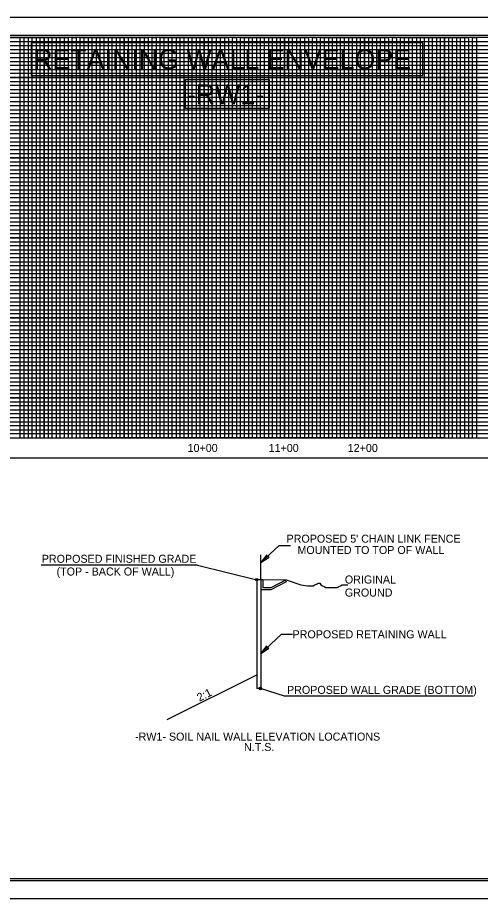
# Model space of a CAD drawing. Extents: x 505237 to 506921, y 424821 to 425921.
# Drawn here: x 505821 to 506398, y 424821 to 425921 of the extents above; entities that cross this region are included whole.
import ezdxf

# ---------------------------------------------------------------- set-up
doc = ezdxf.new("R2010")
doc.units = 0
for name, color, linetype in [('Exist Vertical Profile Ground Line', 7, 'Continuous'), ('Exist Vertical Profile Vertical Axis Label', 7, 'Continuous'), ('Matchline', 7, 'Continuous'), ('Prop Horizontal Alignment Station Label', 7, 'Continuous'), ('Prop North Arrow NAD83 for Plan Sheets CELL', 7, 'Continuous'), ('Prop Vertical Profile Grade', 7, 'Continuous'), ('Scratch_Level_6', 7, 'Continuous'), ('Sheet Clip Boundary CELL', 7, 'Continuous'), ('Sheet Cutting Line CELL', 7, 'Continuous'), ('Sheet DOT Grid CELL', 7, 'Continuous'), ('Sheet Layout Plan Border', 7, 'Continuous'), ('Sheet Plot Border Inside CELL', 7, 'Continuous'), ('Sheet Plot Border Outside CELL', 7, 'Continuous'), ('Sheet Profile Grid Major CELL', 7, 'Continuous'), ('Sheet Sticker Incomplete CELL', 7, 'Continuous'), ('Typical Text Label CELL', 7, 'Continuous')]:
    doc.layers.add(name, color=color, linetype=linetype)

msp = doc.modelspace()

# ---------------------------------------------------------------- linework, layer by layer
at = {"layer": 'Exist Vertical Profile Ground Line'}
for q in [(506123.7, 425218.6), (506174.4, 425212.2)]:
    msp.add_line((506157.2, 425217.9), q, dxfattribs=at)
msp.add_lwpolyline([(506174.4, 425212.2), (506182.6, 425211.1), (506184.7, 425211.1), (506187.8, 425211.1), (506189.8, 425211.1), (506191.9, 425212.2), (506193.9, 425213.2), (506196, 425214.2), (506198.1, 425214.2), (506199.1, 425212.2), (506201.2, 425211.1), (506203.2, 425210.1), (506205.3, 425209.1), (506207.3, 425209.1), (506209.4, 425209.1), (506211.4, 425209.1), (506213.5, 425209.1), (506215.6, 425209.1), (506217.6, 425209.1), (506219.7, 425209.1), (506221.7, 425210.1), (506223.8, 425211.1), (506225.9, 425212.2), (506228.9, 425212.2), (506231, 425212.2), (506233.1, 425212.2)], dxfattribs=at)
at = {"layer": 'Matchline'}
msp.add_line((505403.7, 425870.7), (506703.7, 425870.7), dxfattribs=at)
for points in [[(505778.7, 425395.7), (505828.7, 425395.7), (505828.7, 425895.7), (505878.7, 425895.7), (505878.7, 425395.7), (505928.7, 425395.7), (505928.7, 425895.7), (505978.7, 425895.7), (505978.7, 425395.7), (506028.7, 425395.7), (506028.7, 425395.7), (506028.7, 425895.7), (506078.7, 425895.7), (506078.7, 425395.7), (506128.7, 425395.7), (506128.7, 425895.7), (506178.7, 425895.7), (506178.7, 425395.7), (506228.7, 425395.7), (506228.7, 425895.7), (506278.7, 425895.7), (506278.7, 425395.7), (506328.7, 425395.7), (506328.7, 425895.7), (506378.7, 425895.7), (506378.7, 425395.7), (506428.7, 425395.7)], [(506703.7, 425820.7), (505403.7, 425820.7), (505403.7, 425770.7), (506703.7, 425770.7)], [(506903.7, 425720.7), (505403.7, 425720.7), (505403.7, 425670.7), (506728.7, 425670.7)], [(506903.7, 425620.7), (505403.7, 425620.7), (505403.7, 425570.7), (506903.7, 425570.7)], [(506903.7, 425520.7), (505403.7, 425520.7), (505403.7, 425470.7), (506903.7, 425470.7)], [(506903.7, 425420.7), (505403.7, 425420.7)]]:
    msp.add_lwpolyline(points, dxfattribs=at)
at = {"layer": 'Prop Horizontal Alignment Station Label'}
for p, q in [((505403.7, 425395.7), (506903.7, 425395.7)), ((505403.7, 425370.7), (506903.7, 425370.7)), ((505403.7, 424845.7), (506903.7, 424845.7))]:
    msp.add_line(p, q, dxfattribs=at)
msp.add_lwpolyline([(506903.7, 425895.7), (505403.7, 425895.7), (505403.7, 424845.7), (506903.7, 424845.7)], close=True, dxfattribs=at)
at = {"layer": 'Prop North Arrow NAD83 for Plan Sheets CELL'}
for p, q in [((506147.3, 425261.5), (506124.1, 425240)), ((506147.3, 425261.5), (506161.2, 425261.5)), ((506149.9, 425150.5), (506123.7, 425126.2)), ((506149.9, 425150.5), (506163.9, 425150.5))]:
    msp.add_line(p, q, dxfattribs=at)
for points in [[(506131.9, 425249.9), (506124.1, 425240), (506134.8, 425246.8), (506132.1, 425247.4)], [(506131.4, 425136.1), (506123.7, 425126.2), (506134.3, 425133), (506131.6, 425133.6)]]:
    msp.add_lwpolyline(points, close=True, dxfattribs=at)
at = {"layer": 'Prop Vertical Profile Grade'}
for points in [[(506045.2, 425236.9), (505850.1, 425236.9)], [(506045.2, 425236.9), (506119.1, 425218.6)], [(506153.7, 425073.4), (506123.7, 425082.8)], [(506389.4, 425073.4), (506153.7, 425073.4)]]:
    msp.add_lwpolyline(points, dxfattribs=at)
for centre in [(506119.1, 425218.6), (506123.7, 425082.8)]:
    msp.add_circle(centre, 1.5, dxfattribs=at)
at = {"layer": 'Scratch_Level_6'}
msp.add_lwpolyline([(505903.7, 425845.7), (506353.7, 425845.7), (506353.7, 425395.7), (505903.7, 425395.7)], close=True, dxfattribs=at)
at = {"layer": 'Sheet Clip Boundary CELL'}
for points in [[(506326.7, 425889.2), (505837.4, 425889.2), (505837.4, 425848.3), (506326.7, 425848.3)], [(506030.4, 425843.2), (506134.7, 425843.2), (506134.7, 425807.3), (506030.4, 425807.3)]]:
    msp.add_lwpolyline(points, close=True, dxfattribs=at)
at = {"layer": 'Sheet Cutting Line CELL'}
for p, q in [((506920.7, 425920.7), (505236.7, 425920.7)), ((505903.7, 425370.7), (505953.7, 425370.7)), ((506003.7, 425370.7), (506053.7, 425370.7)), ((506103.7, 425370.7), (506153.7, 425370.7)), ((506203.7, 425370.7), (506253.7, 425370.7)), ((506303.7, 425370.7), (506353.7, 425370.7)), ((505236.7, 424820.7), (506920.7, 424820.7))]:
    msp.add_line(p, q, dxfattribs=at)
for points in [[(505803.7, 425895.7), (505853.7, 425895.7), (505853.7, 425395.7), (505903.7, 425395.7), (505903.7, 425895.7), (505953.7, 425895.7), (505953.7, 425395.7), (506003.7, 425395.7), (506003.7, 425895.7), (506053.7, 425895.7), (506053.7, 425395.7), (506103.7, 425395.7), (506103.7, 425895.7), (506153.7, 425895.7), (506153.7, 425395.7), (506203.7, 425395.7), (506203.7, 425895.7), (506253.7, 425895.7), (506253.7, 425395.7), (506303.7, 425395.7), (506303.7, 425895.7), (506353.7, 425895.7), (506353.7, 425395.7), (506403.7, 425395.7)], [(505403.7, 425845.7), (506703.7, 425845.7)], [(506703.7, 425795.7), (505403.7, 425795.7), (505403.7, 425745.7), (506703.7, 425745.7)], [(506903.7, 425695.7), (505403.7, 425695.7), (505403.7, 425645.7), (506903.7, 425645.7)], [(506903.7, 425595.7), (505403.7, 425595.7), (505403.7, 425545.7), (506903.7, 425545.7)], [(506903.7, 425495.7), (505403.7, 425495.7), (505403.7, 425495.7), (505403.7, 425445.7), (506903.7, 425445.7)]]:
    msp.add_lwpolyline(points, dxfattribs=at)
at = {"layer": 'Sheet DOT Grid CELL'}
for p, q in [((505853.7, 425395.7), (505853.7, 425895.7)), ((505903.7, 425395.7), (505903.7, 425895.7)), ((505953.7, 425395.7), (505953.7, 425895.7)), ((506003.7, 425395.7), (506003.7, 425895.7)), ((506053.7, 425395.7), (506053.7, 425895.7)), ((506103.7, 425395.7), (506103.7, 425895.7)), ((506153.7, 425395.7), (506153.7, 425895.7)), ((506203.7, 425395.7), (506203.7, 425895.7)), ((506253.7, 425395.7), (506253.7, 425895.7)), ((506303.7, 425395.7), (506303.7, 425895.7)), ((506353.7, 425395.7), (506353.7, 425895.7)), ((506703.7, 425845.7), (505403.7, 425845.7)), ((506703.7, 425795.7), (505403.7, 425795.7)), ((506703.7, 425745.7), (505403.7, 425745.7)), ((506903.7, 425695.7), (505403.7, 425695.7)), ((506903.7, 425645.7), (505403.7, 425645.7)), ((506903.7, 425595.7), (505403.7, 425595.7)), ((506903.7, 425545.7), (505403.7, 425545.7)), ((506903.7, 425495.7), (505403.7, 425495.7)), ((506903.7, 425445.7), (505403.7, 425445.7)), ((505403.7, 425370.7), (506903.6, 425370.7))]:
    msp.add_line(p, q, dxfattribs=at)
at = {"layer": 'Sheet Layout Plan Border'}
msp.add_line((506007.5, 425044.1), (506119.1, 425099.9), dxfattribs=at)
at = {"layer": 'Sheet Plot Border Inside CELL'}
msp.add_lwpolyline([(505249.7, 424843.1), (506916.2, 424843.1), (506916.2, 425898.2), (505249.7, 425898.2)], close=True, dxfattribs=at)
at = {"layer": 'Sheet Plot Border Outside CELL'}
msp.add_lwpolyline([(505236.7, 424820.7), (506920.7, 424820.7), (506920.7, 425920.7), (505236.7, 425920.7)], close=True, dxfattribs=at)
at = {"layer": 'Sheet Profile Grid Major CELL'}
for p, q in [((506124.1, 425218.6), (506124.1, 425249.8)), ((506119.1, 425218.6), (506119.1, 425082.8)), ((506126.6, 425218.6), (506119.1, 425218.6)), ((506124.1, 425218.6), (506124.1, 425082.8)), ((506126.6, 425218.6), (506126.6, 425208.6)), ((506155, 425217.9), (506136.6, 425208.6)), ((506155, 425217.9), (506156, 425216)), ((506136.6, 425206.1), (506124.1, 425206.1)), ((506136.6, 425208.6), (506126.6, 425208.6)), ((506156, 425216), (506136.6, 425206.1))]:
    msp.add_line(p, q, dxfattribs=at)
msp.add_lwpolyline([(506124.1, 425082.8), (506119.1, 425082.8)], dxfattribs=at)
at = {"layer": 'Sheet Sticker Incomplete CELL'}
for p, q in [((505453.7, 425890.7), (506703.7, 425890.7)), ((506703.7, 425885.7), (505453.7, 425885.3)), ((505453.7, 425880.7), (506703.7, 425880.7)), ((506703.7, 425760.7), (505453.7, 425760.7)), ((506703.7, 425755.7), (505453.7, 425755.7)), ((506703.7, 425750.7), (505453.7, 425750.7)), ((505453.7, 425740.7), (506703.7, 425740.7)), ((506703.7, 425735.7), (505453.7, 425735.7)), ((505453.7, 425730.7), (506853.7, 425730.7)), ((506853.7, 425710.7), (505453.7, 425710.7)), ((505453.7, 425705.7), (506853.7, 425705.7)), ((506853.7, 425685.7), (505453.7, 425685.7)), ((505453.7, 425680.7), (506853.7, 425680.7)), ((506853.7, 425660.7), (505453.7, 425660.7)), ((505453.7, 425655.7), (506853.7, 425655.7)), ((506853.7, 425650.7), (505453.7, 425650.7)), ((505453.7, 425640.7), (506853.7, 425640.7)), ((506853.7, 425635.7), (505453.7, 425635.7)), ((505453.7, 425630.7), (506853.7, 425630.7)), ((506853.7, 425625.7), (505453.7, 425625.7)), ((505453.7, 425615.7), (506853.7, 425615.7)), ((506853.7, 425610.7), (505453.7, 425610.7)), ((505453.7, 425605.7), (506853.7, 425605.7)), ((506853.7, 425600.7), (505453.7, 425600.7)), ((505453.7, 425590.7), (506853.7, 425590.7)), ((506853.7, 425585.7), (505453.7, 425585.7)), ((505453.7, 425580.7), (506853.7, 425580.7)), ((506853.7, 425575.7), (505453.7, 425575.7)), ((505453.7, 425565.7), (506853.7, 425565.7)), ((506853.7, 425560.7), (505453.7, 425560.7)), ((505453.7, 425555.7), (506853.7, 425555.7)), ((506853.7, 425550.7), (505453.7, 425550.7)), ((505453.7, 425540.7), (506853.7, 425540.7)), ((506853.7, 425535.7), (505453.7, 425535.7)), ((505453.7, 425530.7), (506853.7, 425530.7)), ((506853.7, 425525.7), (505453.7, 425525.7)), ((505453.7, 425515.7), (506853.7, 425515.7)), ((506853.7, 425510.7), (505453.7, 425510.7)), ((506853.7, 425505.7), (505453.7, 425505.7)), ((506853.7, 425500.7), (505453.7, 425500.7)), ((505453.7, 425490.7), (506853.7, 425490.7)), ((506853.7, 425485.7), (505453.7, 425485.7)), ((505453.7, 425480.7), (506853.7, 425480.7)), ((506853.7, 425475.7), (505453.7, 425475.7)), ((505453.7, 425465.7), (506853.7, 425465.7)), ((506853.7, 425460.7), (505453.7, 425460.7)), ((505453.7, 425455.7), (506853.7, 425455.7)), ((506853.7, 425450.7), (505453.7, 425450.7)), ((505453.7, 425440.7), (506853.7, 425440.7)), ((506853.7, 425435.7), (505453.7, 425435.7)), ((505453.7, 425430.7), (506853.7, 425430.7)), ((506853.7, 425425.7), (505453.7, 425425.7)), ((505453.7, 425415.7), (506853.7, 425415.7)), ((506853.7, 425410.7), (505453.7, 425410.7)), ((505453.7, 425405.7), (506853.7, 425405.7))]:
    msp.add_line(p, q, dxfattribs=at)
for points in [[(505818.7, 425395.7), (505823.7, 425395.7), (505823.7, 425895.7), (505833.7, 425895.7), (505833.7, 425395.7), (505838.7, 425395.7), (505838.7, 425895.7), (505843.7, 425895.7), (505843.7, 425395.7), (505848.7, 425395.7), (505848.7, 425895.7), (505858.7, 425895.7), (505858.7, 425395.7), (505863.7, 425395.7), (505863.7, 425895.7), (505868.7, 425895.7), (505868.7, 425395.7), (505873.7, 425395.7), (505873.7, 425895.7), (505883.7, 425895.7), (505883.7, 425395.7), (505888.7, 425395.7), (505888.7, 425895.7), (505893.7, 425895.7), (505893.7, 425395.7), (505898.7, 425395.7), (505898.7, 425895.7), (505908.7, 425895.7), (505908.7, 425395.7), (505913.7, 425395.7), (505913.7, 425895.7), (505918.7, 425895.7), (505918.7, 425395.7), (505923.7, 425395.7), (505923.7, 425895.7), (505933.7, 425895.7), (505933.7, 425395.7), (505938.7, 425395.7), (505938.7, 425895.7), (505943.7, 425895.7), (505943.7, 425395.7), (505948.7, 425395.7), (505948.7, 425895.7), (505958.7, 425895.7), (505958.7, 425395.7), (505963.7, 425395.7), (505963.7, 425895.7), (505968.7, 425895.7), (505968.7, 425395.7), (505973.7, 425395.7), (505973.7, 425895.7), (505983.7, 425895.7)], [(505983.7, 425895.7), (505983.7, 425395.7), (505988.7, 425395.7), (505988.7, 425895.7), (505993.7, 425895.7), (505993.7, 425395.7), (505998.7, 425395.7), (505998.7, 425895.7), (506008.7, 425895.7), (506008.7, 425395.7), (506013.7, 425395.7), (506013.7, 425895.7), (506018.7, 425895.7), (506018.7, 425395.7), (506023.7, 425395.7), (506023.7, 425895.7), (506033.7, 425895.7), (506033.7, 425395.7), (506038.7, 425395.7), (506038.7, 425895.7), (506043.7, 425895.7), (506043.7, 425395.7), (506048.7, 425395.7), (506048.7, 425895.7), (506058.7, 425895.7), (506058.7, 425395.7), (506063.7, 425395.7), (506063.7, 425895.7), (506068.7, 425895.7), (506068.7, 425395.7), (506073.7, 425395.7), (506073.7, 425895.7), (506083.7, 425895.7), (506083.7, 425395.7), (506088.7, 425395.7), (506088.7, 425895.7), (506093.7, 425895.7), (506093.7, 425395.7), (506098.7, 425395.7), (506098.7, 425895.7), (506108.7, 425895.7), (506108.7, 425395.7), (506108.7, 425395.7), (506113.7, 425395.7), (506113.7, 425895.7), (506118.7, 425895.7), (506118.7, 425395.7), (506123.7, 425395.7), (506123.7, 425895.7), (506133.7, 425895.7), (506133.7, 425395.7), (506138.7, 425395.7), (506138.7, 425895.7), (506143.7, 425895.7), (506143.7, 425395.7), (506148.7, 425395.7), (506148.7, 425895.7), (506158.7, 425895.7), (506158.7, 425395.7), (506163.7, 425395.7), (506163.7, 425895.7), (506168.7, 425895.7), (506168.7, 425395.7), (506173.7, 425395.7), (506173.7, 425895.7), (506183.7, 425895.7), (506183.7, 425395.7), (506188.7, 425395.7), (506188.7, 425895.7), (506193.7, 425895.7), (506193.7, 425395.7), (506198.7, 425395.7), (506198.7, 425895.7), (506208.7, 425895.7), (506208.7, 425395.7), (506213.7, 425395.7), (506213.7, 425895.7), (506218.7, 425895.7), (506218.7, 425395.7), (506223.7, 425395.7), (506223.7, 425895.7), (506233.7, 425895.7), (506233.7, 425395.7), (506238.7, 425395.7), (506238.7, 425895.7), (506243.7, 425895.7), (506243.7, 425395.7), (506248.7, 425395.7), (506248.7, 425895.7), (506258.7, 425895.7), (506258.7, 425395.7), (506263.4, 425396.2), (506263.7, 425395.7), (506263.7, 425895.7), (506268.7, 425895.7), (506268.7, 425395.7), (506273.7, 425395.7), (506273.7, 425895.7), (506283.7, 425895.7), (506283.7, 425395.7), (506288.7, 425395.7)], [(506288.7, 425395.7), (506288.7, 425895.7), (506293.7, 425895.7), (506293.7, 425395.7), (506298.7, 425395.7), (506298.7, 425895.7), (506308.7, 425895.7), (506308.7, 425395.7), (506313.7, 425395.7), (506313.7, 425895.7), (506318.7, 425895.7), (506318.7, 425395.7), (506323.7, 425395.7), (506323.7, 425895.7), (506333.7, 425895.7), (506333.7, 425395.7), (506338.7, 425395.7), (506338.7, 425895.7), (506343.7, 425895.7), (506343.7, 425395.7), (506348.7, 425395.7), (506348.7, 425895.7), (506358.7, 425895.7), (506358.7, 425395.7), (506363.7, 425395.7), (506363.7, 425895.7), (506368.7, 425895.7), (506368.7, 425395.7), (506373.7, 425395.7), (506373.7, 425895.7), (506383.7, 425895.7), (506383.7, 425395.7), (506388.7, 425395.7), (506388.7, 425895.7), (506393.7, 425895.7), (506393.7, 425395.7), (506398.7, 425395.7)], [(506703.7, 425875.7), (505453.7, 425875.7), (505453.7, 425865.7), (506703.7, 425865.7)], [(506703.7, 425860.7), (505453.7, 425860.7), (505453.7, 425855.7), (506703.7, 425855.7)], [(506703.7, 425850.7), (505453.7, 425850.7), (505453.7, 425840.7), (506703.7, 425840.7)], [(506703.7, 425835.7), (505453.7, 425835.7), (505453.7, 425830.7), (506703.7, 425830.7)], [(506703.7, 425825.7), (505453.7, 425825.7), (505453.7, 425815.7), (506703.7, 425815.7)], [(506703.7, 425810.7), (505453.7, 425810.7), (505453.7, 425805.7), (506703.7, 425805.7)], [(506703.7, 425800.7), (505453.7, 425800.7), (505453.7, 425790.7), (506703.7, 425790.7)], [(506703.7, 425785.6), (505453.8, 425785.6), (505453.8, 425780.7), (506703.7, 425780.7)], [(506703.7, 425775.7), (505453.7, 425775.7), (505453.7, 425765.7), (506703.7, 425765.7)], [(506853.7, 425725.7), (505453.7, 425725.7), (505453.7, 425715.7), (506853.7, 425715.7)], [(506853.7, 425700.7), (505453.7, 425700.7), (505453.7, 425690.7), (506853.7, 425690.7)], [(506853.7, 425675.7), (505453.7, 425675.7), (505453.7, 425665.7), (506853.7, 425665.7)], [(506853.7, 425400.7), (505453.7, 425400.7)]]:
    msp.add_lwpolyline(points, dxfattribs=at)

# ---------------------------------------------------------------- texts
at = {"layer": 'Exist Vertical Profile Vertical Axis Label'}
for s, p in [('10+00', (506032.8, 425378.2)), ('11+00', (506134, 425378.2)), ('12+00', (506232.8, 425378.2))]:
    msp.add_text(s, height=10, dxfattribs=at).set_placement(p)
at = {"layer": 'Prop North Arrow NAD83 for Plan Sheets CELL'}
for s, p in [("PROPOSED 5' CHAIN LINK FENCE ", (506156.4, 425264.9)), ('MOUNTED TO TOP OF WALL', (506170, 425250.8)), ('PROPOSED RETAINING WALL', (506163.9, 425145.5))]:
    msp.add_text(s, height=10, dxfattribs=at).set_placement(p)
at = {"layer": 'Prop Vertical Profile Grade'}
for s, p in [('PROPOSED FINISHED GRADE', (505850.7, 425239.8)), ('(TOP - BACK OF WALL)', (505869.2, 425223.9)), ('-RW1- SOIL NAIL WALL ELEVATION LOCATIONS', (505967.2, 425017.7)), ('N.T.S.', (506103.3, 425004.7))]:
    msp.add_text(s, height=10, dxfattribs=at).set_placement(p)
msp.add_text('PROPOSED WALL GRADE (BOTTOM)', height=10, rotation=360, dxfattribs=at).set_placement((506157, 425076.1))
at = {"layer": 'Sheet Layout Plan Border'}
for s, p in [('RETAINING WALL ENVELOPE', (505840, 425856.2)), ('-RW1-', (506031.9, 425812.3))]:
    msp.add_text(s, height=25, dxfattribs=at).set_placement(p)
for s, p in [('ORIGINAL', (506229.2, 425213.9)), ('GROUND', (506229.2, 425197.6))]:
    msp.add_text(s, height=10, rotation=360, dxfattribs=at).set_placement(p)
at = {"layer": 'Typical Text Label CELL'}
msp.add_text('2:1', height=10, rotation=26.5651, dxfattribs=at).set_placement((506047.6, 425066.3))

doc.saveas('drawing.dxf')
